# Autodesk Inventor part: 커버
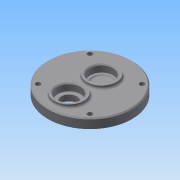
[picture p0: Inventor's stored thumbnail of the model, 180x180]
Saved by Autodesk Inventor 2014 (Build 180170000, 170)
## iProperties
Created: 2015-06
Part Number: 커버
Material: 일반
Document SubType Name: Modeling
Designer: AMC
Density: 1 g/cm^3
Appearance: 기본값
Author: AMC
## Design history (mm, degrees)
sketch "스케치1"
  geometry: C1 r 40 at (0, 0); 1 further point
  constraints: 1 centre point, 1 coincident
  dimensions: "d0" = 80 diameter of C1
extrude "돌출1" new body sketch "스케치1" distance "d1" = 9; taper "d2" = 0 deg
sketch "스케치5"
  geometry: C1 r 40 at (0, 0) reference; C2 r 14 at (0, 11); C3 r 14 at (0, -20)
  constraints: 2 centre point
  dimensions: "d21" = 28 diameter of C3; "d22" = 28 diameter of C2; "d23" = 0 horizontal distance of C1.centre C2.centre; "d24" = 11 distance of C1.centre C2.centre; "d25" = 0 horizontal distance of C1.centre C3.centre; "d26" = 20 distance of C1.centre C3.centre
extrude "돌출4" join sketch "스케치5" distance "d27" = 3; taper "d28" = 0 deg
sketch "스케치6"
  geometry: C1 r 40 at (0, 0) reference; C2 r 14 at (0, -20)
  constraints: 1 centre point
  dimensions: "d29" = 28 diameter of C2; "d30" = 0 horizontal distance of C1.centre C2.centre; "d31" = 20 distance of C1.centre C2.centre
extrude "돌출5" join sketch "스케치6" distance "d32" = 4; taper "d33" = 0 deg
sketch "스케치7"
  geometry: L1 (40, 9)-(40, 0) reference; L2 (40, 0)-(-6, 0) reference; L3 (-6, 0)-(-6, -4) reference; L4 (-6, -4)-(-34, -4) reference; L5 (-34, -4)-(-34, 0) reference; L6 (-34, 0)-(-40, 0) reference; L7 (-40, 0)-(-40, 9) reference; L8 (-40, 9)-(-34, 9) reference; L9 (-34, 9)-(-34, 12) reference; L10 (-34, 12)-(-6, 12) reference; L11 (-6, 12)-(-6, 9) reference; L12 (-6, 9)-(-3, 9) reference; L13 (-3, 9)-(-3, 12) reference; L14 (-3, 12)-(25, 12) reference; L15 (25, 12)-(25, 9) reference; L16 (25, 9)-(40, 9) reference; L17 (-20, -4)-(-20, 12); L18 (-9, -4)-(-9, 3); L19 (-9, 3)-(-12.5, 3); L20 (-12.5, 3)-(-12.5, 5); L21 (-12.5, 5)-(-9, 5); L22 (-9, 5)-(-9, 12); L23 (11, 12)-(11, 4); L24 (11, 4)-(20, 4); L25 (20, 4)-(20, 5); L26 (20, 5)-(22, 5); L27 (22, 5)-(22, 12); 1 further point
  constraints: 22 end point, 6 perpendicular, 4 parallel, 3 midpoint, 3 point on line
  dimensions: "d34" = 22 diameter of L22 L17; "d35" = 15 diameter of L20 L17; "d36" = 22 diameter of L18 L17; "d37" = 7 distance between parallel lines of L4 L19; "d38" = 2 distance between parallel lines of L21 L19; "d39" = 22 diameter of L27 L23; "d40" = 18 diameter of L25 L23; "d41" = 1 distance between parallel lines of L26 L24; "d42" = 7 distance between parallel lines of L14 L26
  node "절단 모서리 투영2"
revolve "회전1" stored, may be unused: angle "d43" = 90 deg
revolve "회전2" stored, may be unused: angle "d44" = 90 deg
sketch "스케치8"
  geometry: L1 (0, 0)-(-24.749, 24.749); L2 (0, 0)-(35, 0); C1 r 40 at (0, 0) reference
  constraints: 4 end point, 1 equal length, 1 horizontal
  dimensions: "d45" = 35 distance of L1.start L1.end; "d46" = 135 deg angle of L2 L1
hole "구멍1" sketch "스케치8" at (-24.749, 24.749) diameter "d47" = 4.5; stored, may be unused: countersink angle "d51" = 90 deg, drill point angle "d53" = 118 deg; dims "d48" = 6, "d49" = 8, "d50" = 4.4, "d52" = 8
fillet "모깎기1" dims "d57" = 0.3
fillet "모깎기2" dims "d58" = 2
chamfer "모따기1" distance "d59" = 1; stored, may be unused: second distance "d60" = 2, angle "d61" = 45 deg
fillet "모깎기3" dims "d62" = 2
chamfer "모따기2" distance "d63" = 1; stored, may be unused: second distance "d64" = 2, angle "d65" = 45 deg
node "솔리드1"
pattern_circular "원형 패턴1" dims angle "d55" = 360 deg
